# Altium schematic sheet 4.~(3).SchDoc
size 420 x 297 mm
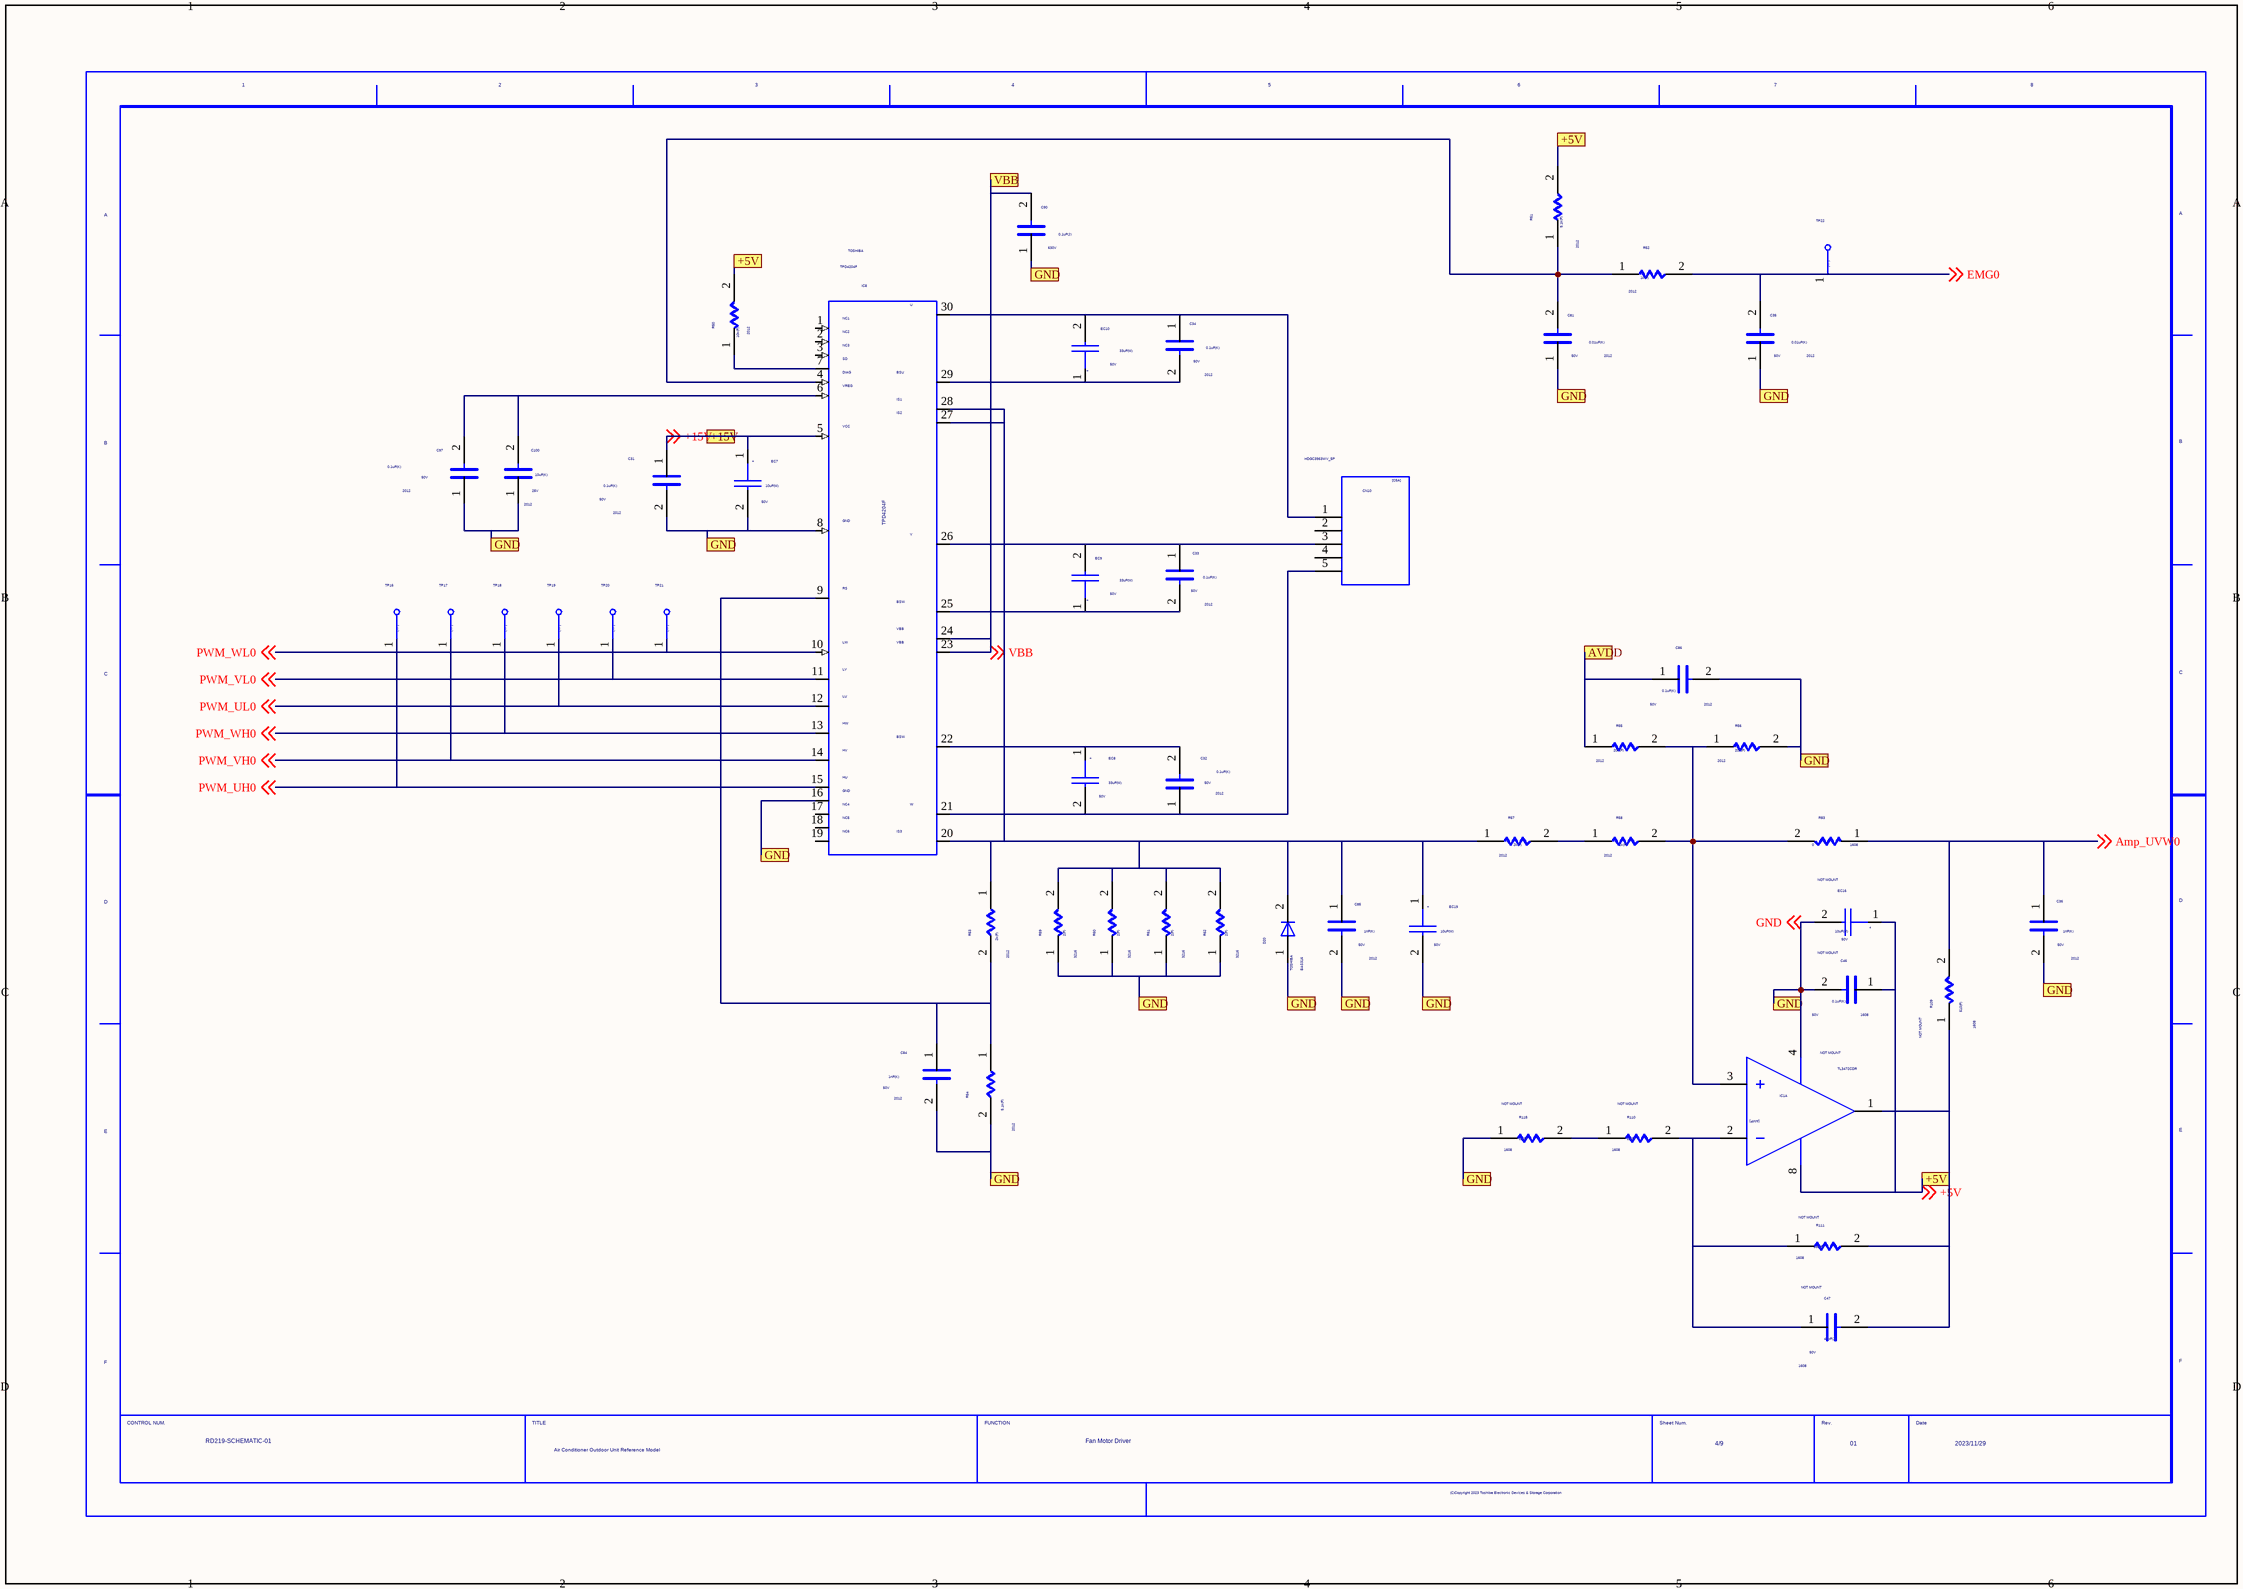
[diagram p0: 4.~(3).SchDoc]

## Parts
C31  VAL2: 50V  SIZECODESMD: 2012  VAL1: 0.1uF(K)  (hidden comment: C)
C32  VAL2: 50V  SIZECODESMD: 2012  VAL1: 0.1uF(K)  (hidden comment: C)
C33  VAL2: 50V  SIZECODESMD: 2012  VAL1: 0.1uF(K)  (hidden comment: C)
C34  VAL2: 50V  SIZECODESMD: 2012  VAL1: 0.1uF(K)  (hidden comment: C)
C35  VAL2: 50V  SIZECODESMD: 2012  VAL1: 0.01uF(K)  (hidden comment: C)
C36  VAL2: 50V  SIZECODESMD: 2012  VAL1: 1nF(K)  (hidden comment: C)
C46  NOTMOUNT: NOT MOUNT  VAL1: 0.1uF(K)  VAL2: 50V  SIZECODESMD: 1608  (hidden comment: C)
C47  NOTMOUNT: NOT MOUNT  VAL1: 47pF(J)  VAL2: 50V  SIZECODESMD: 1608  (hidden comment: C)
C81  VAL2: 50V  SIZECODESMD: 2012  VAL1: 0.01uF(K)  (hidden comment: C)
C84  VAL2: 50V  SIZECODESMD: 2012  VAL1: 1nF(K)  (hidden comment: C)
C85  VAL2: 50V  SIZECODESMD: 2012  VAL1: 1nF(K)  (hidden comment: C)
C86  VAL2: 50V  SIZECODESMD: 2012  VAL1: 0.1uF(K)  (hidden comment: C)
C90  VAL2: 630V  VAL1: 0.1uF(J)  (hidden comment: C)
C97  VAL2: 50V  SIZECODESMD: 2012  VAL1: 0.1uF(K)  (hidden comment: C)
C100  VAL2: 25V  SIZECODESMD: 2012  VAL1: 10uF(K)  (hidden comment: C)
CN10  VAL3: HDGC3963WV_5P  (hidden comment: C5A)
D20  USERCOMPTEXT3: TOSHIBA  VAL3: BAS316  (hidden comment: D_CUSTOM)
EC7  VAL2: 50V  VAL1: 10uF(M)  (hidden comment: EC)
EC8  VAL2: 50V  VAL1: 33uF(M)  (hidden comment: EC)
EC9  VAL2: 50V  VAL1: 33uF(M)  (hidden comment: EC)
EC10  VAL2: 50V  VAL1: 33uF(M)  (hidden comment: EC)
EC16  NOTMOUNT: NOT MOUNT  VAL2: 50V  VAL1: 10uF(M)  (hidden comment: EC)
EC19  VAL2: 50V  VAL1: 10uF(M)  (hidden comment: EC)
IC1  NOTMOUNT: NOT MOUNT  VAL3: TL3472CDR  (hidden comment: AMP_1)  (part A of 2)
IC8  USERCOMPTEXT3: TOSHIBA  (hidden comment: TPD4204F)
R50  SIZECODESMD: 2012  VAL1: 10k(F)  (hidden comment: R)
R51  SIZECODESMD: 2012  VAL1: 5.1k(F)  (hidden comment: R)
R52  SIZECODESMD: 2012  VAL1: 1k(F)  (hidden comment: R)
R53  SIZECODESMD: 2012  VAL1: 2k(F)  (hidden comment: R)
R54  SIZECODESMD: 2012  VAL1: 5.1k(F)  (hidden comment: R)
R55  SIZECODESMD: 2012  VAL1: 20k(F)  (hidden comment: R)
R56  SIZECODESMD: 2012  VAL1: 20k(F)  (hidden comment: R)
R57  SIZECODESMD: 2012  VAL1: 2k(F)  (hidden comment: R)
R58  SIZECODESMD: 2012  VAL1: 2k(F)  (hidden comment: R)
R59  SIZECODESMD: 3216  VAL1: 2(F)  (hidden comment: R)
R60  SIZECODESMD: 3216  VAL1: 2(F)  (hidden comment: R)
R61  SIZECODESMD: 3216  VAL1: 2(F)  (hidden comment: R)
R62  SIZECODESMD: 3216  VAL1: 2(F)  (hidden comment: R)
R83  SIZECODESMD: 1608  VAL1: 0  (hidden comment: R)
R109  NOTMOUNT: NOT MOUNT  SIZECODESMD: 1608  VAL1: 510(F)  (hidden comment: R)
R110  NOTMOUNT: NOT MOUNT  SIZECODESMD: 1608  VAL1: 2k(F)  (hidden comment: R)
R111  NOTMOUNT: NOT MOUNT  SIZECODESMD: 1608  VAL1: 10k(F)  (hidden comment: R)
R115  NOTMOUNT: NOT MOUNT  SIZECODESMD: 1608  VAL1: 2k(F)  (hidden comment: R)
TP16  TP  (value not drawn)
TP17  TP  (value not drawn)
TP18  TP  (value not drawn)
TP19  TP  (value not drawn)
TP20  TP  (value not drawn)
TP21  TP  (value not drawn)
TP22  TP  (value not drawn)
U?  DATE: 2023/11/29  FUNCTION: Fan Motor Driver  TITLE: Air Conditioner Outdoor Unit / Reference Model  DRAWINGNUMBER: RD219-SCHEMATIC-01  SHEETNUMBER: 4/9  REVISION: 01  (hidden comment: WAKU_DEF100)

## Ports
+5V, +15V, AVDD, GND, VBB

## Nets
+15V: C31.1 EC7.1 IC8.5 ; off-sheet +15V, port +15V
Amp_UVW0: C36.1 R83.1 R109.2 ; off-sheet Amp_UVW0
AVDD: C86.1 R55.1 ; port AVDD
EMG0: C35.2 R52.2 TP22.1 ; off-sheet EMG0
GND: C31.2 C35.1 C36.2 C46.2 C81.1 C84.2 C85.2 C86.2 C90.1 C97.1 C100.1 D20.1 EC7.2 EC16.2 EC19.2 IC1.4 IC8.8 IC8.16 R54.2 R56.2 R59.1 R60.1 R61.1 R62.1 R115.1 ; off-sheet GND, port GND
NetC32_1: C32.1 CN10.5 EC8.2 IC8.21
NetC32_2: C32.2 EC8.1 IC8.22
NetC33_1: C33.1 CN10.3 EC9.2 IC8.26
NetC33_2: C33.2 EC9.1 IC8.25
NetC34_1: C34.1 CN10.1 EC10.2 IC8.30
NetC34_2: C34.2 EC10.1 IC8.29
NetC47_1: C47.1 IC1.2 R110.2 R111.1
NetC47_2: C46.1 C47.2 EC16.1 IC1.1 IC1.8 R50.2 R51.2 R109.1 R111.2 ; off-sheet +5V, port +5V  [also labelled +5V]
NetC81_2: C81.2 IC8.4 R51.1 R52.1
NetC84_1: C84.1 IC8.9 R53.2 R54.1
NetC85_1: C85.1 D20.2 EC19.1 IC8.20 IC8.27 IC8.28 R53.1 R57.1 R59.2 R60.2 R61.2 R62.2
NetC97_2: C97.2 C100.2 IC8.6
NetIC1_3: IC1.3 R55.2 R56.1 R58.2 R83.2
NetIC8_7: IC8.7 R50.1
NetR57_2: R57.2 R58.1
NetR110_1: R110.1 R115.2
PWM_UH0: IC8.15 TP16.1 ; off-sheet PWM_UH0
PWM_UL0: IC8.12 TP19.1 ; off-sheet PWM_UL0
PWM_VH0: IC8.14 TP17.1 ; off-sheet PWM_VH0
PWM_VL0: IC8.11 TP20.1 ; off-sheet PWM_VL0
PWM_WH0: IC8.13 TP18.1 ; off-sheet PWM_WH0
PWM_WL0: IC8.10 TP21.1 ; off-sheet PWM_WL0
VBB: C90.2 IC8.23 IC8.24 ; off-sheet VBB, port VBB

Not connected (* = marked no-connect by the designer): CN10 2 4; IC8 1 2 3 17 18 19

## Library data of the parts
C31-C34 C86 C97 = C: OriginalSymbolOrigin: (2540,7620); COMP: AC0805KRX7R9BB104
C35 C81 = C: OriginalSymbolOrigin: (2540,7620); COMP: AC0805KRX7R9BB103
C36 C84 C85 = C: OriginalSymbolOrigin: (2540,7620); COMP: AC0805KRX7R9BB102
C46 = C: OriginalSymbolOrigin: (2540,7620); COMP: AC0603KRX7R9BB104
C47 = C: OriginalSymbolOrigin: (2540,7620); VAL3: AC0603JRNPO9BN470
C90 = C: OriginalSymbolOrigin: (2540,7620); COMP: CBB22_104J630V
C100 = C: OriginalSymbolOrigin: (2540,7620); COMP: AC0805KKX5R8BB106
CN10 = C5A: SAVEAREA0: -9193,-269,29123,23485; TIME: 08:44:29; UPDATEUSER: fukuda-y; UPDATETIME: 10:06:49; SAVECOUNT: 4; OriginalSymbolOrigin: (2540,20320); COMPCOMMENT: VH3.96/5P
D20 = D_CUSTOM: SAVEAREA0: -1668,-97,14265,7829; SAVECOUNT: 4; TIME: 14:49:55; UPDATEUSER: w20165dm; UPDATETIME: 16:47:49; OriginalSymbolOrigin: (5080,5080)
EC7 = EC: SAVEAREA0: -1432,-1528,20311,14389; SAVECOUNT: 53; TIME: 15:02:55; UPDATEUSER: w20165dm; UPDATETIME: 16:35:05; OriginalSymbolOrigin: (2540,10160); VAL3: ESS106M050AE2AA
EC8-EC10 = EC: SAVEAREA0: -1432,-1528,20311,14389; SAVECOUNT: 53; TIME: 15:02:55; UPDATEUSER: w20165dm; UPDATETIME: 16:35:05; OriginalSymbolOrigin: (2540,10160); VAL3: ESH336M050AE3AA
EC16 EC19 = EC: SAVEAREA0: -1432,-1528,20311,14389; SAVECOUNT: 53; TIME: 15:02:55; UPDATEUSER: w20165dm; UPDATETIME: 16:35:05; OriginalSymbolOrigin: (2540,10160); VAL3: ESS106M050AE2AA; COMP: 50V10UF_5X11
IC1 = AMP_1: SAVEAREA0: -6226,-235,36343,20943; TIME: 17:09:52; UPDATEUSER: w20165dm; SAVECOUNT: 1; OriginalSymbolOrigin: (5080,20320); CaptureCellPackProp: AMP_1A; FUNCN: IC1_1
IC8 = TPD4204F: TIME: 16:32:01; UPDATEUSER: sptcae13; UPDATETIME: 10:27:40; SAVECOUNT: 16; SAVEAREA0: -113524,-1329,136787,112726; OriginalSymbolOrigin: (2540,106680)
R50 = R: OriginalSymbolOrigin: (5080,5080); COMP: AC08005FR_0710KL; VAL3: AC0805FR-0710KL; VAL2: 125mW
R51 R54 = R: OriginalSymbolOrigin: (5080,5080); COMP: AC0805FR_075K1L; VAL3: AC0805FR-075K1L; VAL2: 125mW
R52 = R: OriginalSymbolOrigin: (5080,5080); COMP: AC0805FR_071KL; VAL3: AC0805FR-071KL; VAL2: 125mW
R53 R57 R58 = R: OriginalSymbolOrigin: (5080,5080); COMP: AC0805FR_072KL; VAL3: AC0805FR-072KL; VAL2: 125mW
R55 R56 = R: OriginalSymbolOrigin: (5080,5080); COMP: AC0805FR_0720KL; VAL3: AC0805FR-0720KL; VAL2: 125mW
R59-R62 = R: OriginalSymbolOrigin: (5080,5080); COMP: AC1206FR_072RL; VAL3: AC1206FR-072RL; VAL2: 250mW
R83 = R: OriginalSymbolOrigin: (5080,5080); COMP: AC0603FR_070RL; VAL2: 100mW
R109 = R: OriginalSymbolOrigin: (5080,5080); COMP: AC0603FR_07510RL; VAL2: 100mW
R110 R115 = R: OriginalSymbolOrigin: (5080,5080); COMP: AC0603FR_072KL; VAL2: 100mW
R111 = R: OriginalSymbolOrigin: (5080,5080); COMP: AC0603FR_0710KL; VAL2: 100mW
TP16 = TP_Dup1: TIME: 16:12:21; UPDATEUSER: fukuda-y; UPDATETIME: 16:18:11; SAVECOUNT: 2; SAVEAREA0: -242,-92,12810,7836; OriginalSymbolOrigin: (0,7620); COMPCOMMENT: UH0; VAL3: ZXD
TP17 = TP_Dup1: TIME: 16:12:21; UPDATEUSER: fukuda-y; UPDATETIME: 16:18:11; SAVECOUNT: 2; SAVEAREA0: -242,-92,12810,7836; OriginalSymbolOrigin: (0,7620); COMPCOMMENT: VH0; VAL3: ZXD
TP18 = TP_Dup1: TIME: 16:12:21; UPDATEUSER: fukuda-y; UPDATETIME: 16:18:11; SAVECOUNT: 2; SAVEAREA0: -242,-92,12810,7836; OriginalSymbolOrigin: (0,7620); COMPCOMMENT: WH0; VAL3: ZXD
TP19 = TP_Dup1: TIME: 16:12:21; UPDATEUSER: fukuda-y; UPDATETIME: 16:18:11; SAVECOUNT: 2; SAVEAREA0: -242,-92,12810,7836; OriginalSymbolOrigin: (0,7620); COMPCOMMENT: UL0; VAL3: ZXD
TP20 = TP_Dup1: TIME: 16:12:21; UPDATEUSER: fukuda-y; UPDATETIME: 16:18:11; SAVECOUNT: 2; SAVEAREA0: -242,-92,12810,7836; OriginalSymbolOrigin: (0,7620); COMPCOMMENT: VL0; VAL3: ZXD
TP21 = TP_Dup1: TIME: 16:12:21; UPDATEUSER: fukuda-y; UPDATETIME: 16:18:11; SAVECOUNT: 2; SAVEAREA0: -242,-92,12810,7836; OriginalSymbolOrigin: (0,7620); COMPCOMMENT: WL0; VAL3: ZXD
TP22 = TP_Dup1: TIME: 16:12:21; UPDATEUSER: fukuda-y; UPDATETIME: 16:18:11; SAVECOUNT: 2; SAVEAREA0: -242,-92,12810,7836; OriginalSymbolOrigin: (0,7620); COMPCOMMENT: EMG0; VAL3: ZXD
U? = WAKU_DEF100: PLOTTIME: HH:MM; SAVEAREA0: -45080,-4508,463680,304612; TIME: 18:02:41; UPDATEUSER: sptcae13; UPDATETIME: 08:19:30; SAVECOUNT: 8; OriginalSymbolOrigin: (10160,284480)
